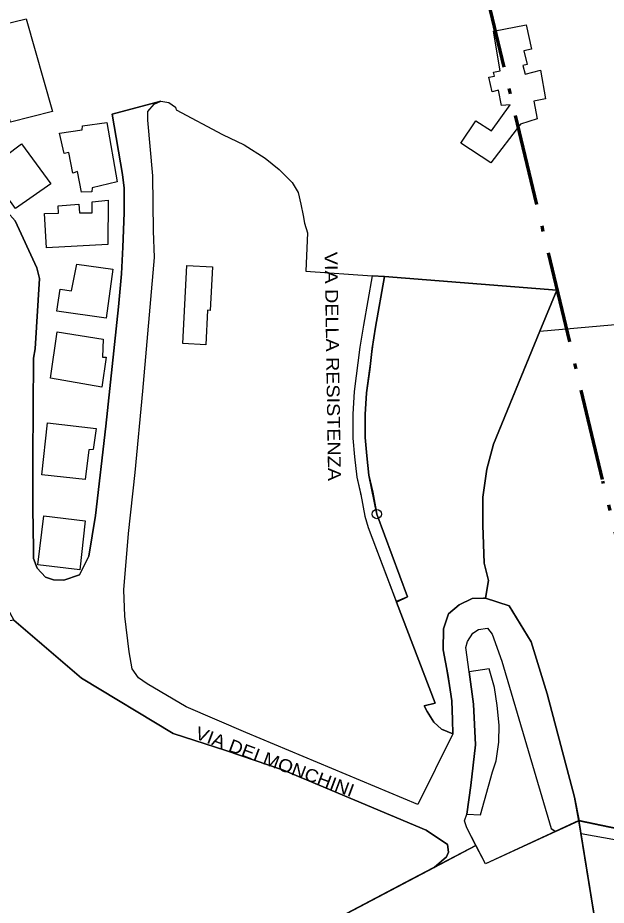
# Model space of a CAD drawing. Extents: x 654952 to 658955, y 890426 to 894481.
# Drawn here: x 657884.3 to 658012.7, y 891148.5 to 891342 of the extents above; entities that cross this region are included whole.
import ezdxf

# ---------------------------------------------------------------- set-up
doc = ezdxf.new("R2010")
doc.units = 0
doc.header["$LTSCALE"] = 4
doc.header["$PDMODE"] = 32
doc.header["$PDSIZE"] = 2
doc.linetypes.add('DOT_DASHED', pattern=[7.7, 5, -1.2, 0.3, -1.2])
for name, color, linetype, lineweight in [('1', 7, 'Continuous', 25), ('14', 7, 'Continuous', 25), ('17', 7, 'Continuous', 25), ('18', 7, 'Continuous', 25), ('19', 7, 'Continuous', 25), ('4', 7, 'Continuous', 25), ('45', 7, 'Continuous', 25), ('5', 7, 'Continuous', 25), ('55', 7, 'Continuous', 25), ('6', 7, 'Continuous', 25), ('8', 7, 'Continuous', 25), ('9', 7, 'Continuous', 25)]:
    doc.layers.add(name, color=color, linetype=linetype, lineweight=lineweight)
doc.layers.add('58', color=7, linetype='Continuous')

msp = doc.modelspace()

# ---------------------------------------------------------------- linework, layer by layer
at = {"layer": '1'}
for points in [[(657837.7, 891323.26), (657840.4, 891320.51), (657845.62, 891316.26), (657850.47, 891313.45), (657857.34, 891310.34), (657865.89, 891307.18), (657872.64, 891304.78), (657879.11, 891301.28), (657882.13, 891299.62), (657883.82, 891297.74), (657888.48, 891287.53), (657889.08, 891285.16), (657888.12, 891269.81), (657887.77, 891267.8)], [(657903.58, 891252.96), (657906.29, 891278.97), (657906.97, 891286.22), (657907.28, 891292.01), (657907.58, 891299.5), (657907.58, 891304.88), (657907.21, 891307.87), (657904.93, 891321.02), (657915.56, 891323.86)], [(657915.56, 891323.86), (657917.29, 891323.59), (657918.78, 891322.54), (657918.9, 891321.96)], [(657918.9, 891321.96), (657929.02, 891316.61), (657933.72, 891314.31), (657938.3, 891311.39), (657941.35, 891308.94), (657944.2, 891306.13), (657945.48, 891303.91), (657946.11, 891301.37), (657946.58, 891298.89), (657946.89, 891297.28), (657947.53, 891295.12), (657947.16, 891286.77)], [(657947.16, 891286.77), (657947.16, 891286.77), (657961.66, 891285.78), (657964.34, 891285.58), (658001.92, 891282.67)], [(658001.92, 891282.67), (657998.2, 891273.72), (657988.12, 891249.03)], [(657887.77, 891267.8), (657887.66, 891246.01), (657887.64, 891240.59), (657887.61, 891234.99)], [(657897.82, 891220.6), (657899.85, 891224.62), (657901.3, 891233.53), (657903.58, 891252.96)], [(657988.12, 891249.03), (657986.66, 891243.62), (657985.8, 891237.53), (657985.79, 891231.43), (657986.1, 891223.09), (657986.1, 891223.09), (657987.02, 891219.31), (657986.38, 891215.5)], [(657887.61, 891234.99), (657887.82, 891226.31), (657887.76, 891224.11), (657888.55, 891222.04), (657890.43, 891220.03), (657892.18, 891219.47), (657894.41, 891219.41), (657897.82, 891220.6)], [(657986.38, 891215.5), (657991.53, 891213.82), (657996.3, 891205.97)], [(657996.3, 891205.97), (657999.79, 891194.64), (658005.79, 891172.08), (658006.76, 891166.92)], [(658006.76, 891166.92), (658033.23, 891161.37), (658037.2, 891170.9), (658047.02, 891166.87), (658052.34, 891180.28), (658045.56, 891182.36), (658047.89, 891197.88), (658050.23, 891196.88)], [(658045.52, 891182.46), (658052.3, 891180.38), (658046.98, 891166.97), (658037.16, 891171), (658033.19, 891161.47), (658006.72, 891167.02), (658006.74, 891166.97), (658033.19, 891161.47), (658006.74, 891166.97)], [(658045.52, 891182.46), (658052.3, 891180.38), (658046.98, 891166.97), (658037.16, 891171), (658033.19, 891161.47), (658006.72, 891167.02), (658006.74, 891166.97)], [(658006.74, 891166.97), (657986.34, 891157.53), (657984.28, 891161.53), (657968.84, 891153.47), (657953.43, 891145.35)], [(658006.73, 891166.96), (657986.34, 891157.53), (657984.28, 891161.53), (657968.84, 891153.47), (657953.43, 891145.35)], [(658006.72, 891167.02), (658012.28, 891132.38), (658008.65, 891129.88), (657997.35, 891113.85), (657997.53, 891112.42), (657995.02, 891111.66), (657997.56, 891102.12), (658009.55, 891082.21)], [(658009.55, 891082.21), (657997.56, 891102.12), (657995.02, 891111.66), (657997.53, 891112.42), (657997.35, 891113.85), (658008.65, 891129.88), (658012.28, 891132.38), (658006.73, 891166.96)]]:
    msp.add_lwpolyline(points, dxfattribs=at)
at = {"layer": '14'}
msp.add_lwpolyline([(657982.82, 891199.41), (657982.05, 891204.72), (657982.4, 891206.04), (657983.6, 891207.88), (657984.84, 891208.66), (657986.83, 891208.91), (657987.79, 891207.65), (657989.91, 891201.71), (657989.91, 891201.71), (658000.67, 891165.24), (658001.7, 891164.59), (657986.34, 891157.53), (657982.28, 891165.41), (657981.78, 891166.96), (657982.32, 891168.35), (657985.28, 891168.21), (657987.87, 891177.62), (657988.67, 891179.99), (657989.24, 891184.09), (657989.34, 891187.82), (657988.9, 891192.06), (657988.3, 891196.02), (657987.16, 891200.07)], close=True, dxfattribs=at)
at = {"layer": '17'}
for points in [[(657978.08, 891161.76), (657973.4, 891164.86), (657942.34, 891177.94), (657929.71, 891182.26), (657918.26, 891185.94), (657898.29, 891198.03), (657883.47, 891210.7), (657878.12, 891209.84), (657855.72, 891210.15), (657829.85, 891209.87), (657828.3, 891222.06)], [(657953.53, 891145.36), (657975.13, 891156.76), (657977.86, 891159.09), (657978.28, 891160.13), (657978.08, 891161.76)]]:
    msp.add_lwpolyline(points, dxfattribs=at)
at = {"layer": '18'}
for points in [[(657961.66, 891285.78), (657959.76, 891275.02), (657958.99, 891270.24), (657958.99, 891270.24), (657957.75, 891260.54), (657957.46, 891255.57), (657957.45, 891250.37), (657957.79, 891246.26), (657958.31, 891241.87), (657959.2, 891237.99), (657959.17, 891238.11), (657960.02, 891233.34), (657960.76, 891230.89), (657966.88, 891214.72), (657969.35, 891215.76)], [(657961.8, 891238.58), (657960.95, 891242.32), (657960.45, 891246.53), (657960.12, 891250.48), (657960.13, 891255.49), (657960.41, 891260.27), (657961.15, 891265.34), (657961.64, 891269.89), (657962.39, 891274.58), (657964.34, 891285.58), (657961.66, 891285.78)], [(657969.35, 891215.76), (657962.65, 891233.81), (657961.8, 891238.58)], [(657988.6, 891194.04), (657988.3, 891196.02), (657987.16, 891200.07), (657982.82, 891199.41), (657983.72, 891192.35), (657984.15, 891183.49), (657983.15, 891174.64)], [(657989.34, 891187.82), (657988.9, 891192.06), (657988.6, 891194.04)], [(657983.15, 891174.64), (657982.32, 891168.35), (657985.28, 891168.21), (657987.87, 891177.62), (657988.67, 891179.99), (657989.24, 891184.09), (657989.34, 891187.82)]]:
    msp.add_lwpolyline(points, dxfattribs=at)
at = {"layer": '19'}
for points in [[(657964.34, 891285.58), (657962.39, 891274.58), (657961.64, 891269.89), (657961.15, 891265.34), (657960.41, 891260.27), (657960.13, 891255.49), (657960.12, 891250.48), (657960.45, 891246.53), (657960.95, 891242.32), (657961.8, 891238.58), (657962.65, 891233.81)], [(657994.23, 891263.99), (657998.2, 891273.72), (658001.92, 891282.67), (657964.34, 891285.58)], [(657986.38, 891215.5), (657987.02, 891219.31), (657986.1, 891223.09), (657986.1, 891223.09), (657985.79, 891231.43), (657985.8, 891237.53), (657986.66, 891243.62), (657988.12, 891249.03), (657994.23, 891263.99)], [(657962.65, 891233.81), (657969.35, 891215.76), (657966.88, 891214.72), (657975.39, 891192.57), (657972.96, 891192.01), (657973.67, 891190.77), (657975.07, 891188.45), (657976.78, 891186.91), (657979.26, 891185.89), (657979.15, 891188.93), (657979, 891193.06), (657978.13, 891198.84), (657977.14, 891204.22), (657977.21, 891208.77), (657978.31, 891212.06), (657980.61, 891214.03), (657983.45, 891215.38), (657985.9, 891215.47), (657986.38, 891215.5)]]:
    msp.add_lwpolyline(points, dxfattribs=at)
msp.add_point((657962.65, 891233.81), dxfattribs=at)
at = {"layer": '4'}
for points in [[(657886.17, 891341.82), (657891.92, 891321.58), (657882.74, 891319.3), (657877.46, 891339.66)], [(657987.49, 891310.42), (657980.99, 891314.7), (657984.23, 891319.58), (657987.68, 891317.36), (657991.73, 891323.08), (657989.86, 891322.9), (657989.22, 891326.24), (657987.85, 891325.9), (657987.08, 891329.06), (657988.32, 891329.32), (657988.08, 891330.16), (657989.54, 891330.46), (657988.13, 891339.12), (657995.24, 891340.5), (657996.38, 891335.2), (657994.71, 891334.8), (657995.43, 891331.84), (657994.51, 891331.64), (657995.01, 891329.76), (657998.34, 891330.58), (657999.48, 891324.34), (657996.91, 891323.88), (657997.63, 891320), (657994.02, 891318.86)], [(657903.75, 891319.2), (657906.05, 891306.24), (657900.56, 891304.96), (657900.54, 891304.08), (657898.26, 891304.02), (657897.41, 891308.52), (657896.35, 891308.18), (657895.51, 891312.64), (657894.44, 891312.44), (657893.49, 891316.86), (657898.43, 891317.6), (657898.47, 891318.5)], [(657883.88, 891300.46), (657877.67, 891308.94), (657885.2, 891314.52), (657891.55, 891305.84)], [(657904.02, 891292.58), (657890.59, 891291.88), (657890.17, 891299.36), (657893.22, 891299.4), (657893.14, 891301.02), (657897.68, 891301.4), (657897.83, 891299.48), (657900.6, 891299.52), (657900.56, 891301.9), (657904.04, 891302.24)], [(657905.08, 891287.22), (657903.6, 891276.54), (657892.88, 891278.04), (657893.57, 891282.84), (657896.09, 891282.48), (657897.2, 891288.32)], [(657891.48, 891263.44), (657892.96, 891273.56), (657903, 891271.98), (657902.81, 891268), (657903.6, 891268.02), (657902.67, 891261.48)], [(657889.61, 891242.36), (657890.87, 891253.74), (657901.44, 891252.44), (657900.81, 891247.88), (657899.86, 891247.82), (657899.07, 891241.36)], [(657888.73, 891222.78), (657890.04, 891233.42), (657899.08, 891232.34), (657897.91, 891221.66)]]:
    msp.add_lwpolyline(points, close=True, dxfattribs=at)
at = {"layer": '45', "linetype": 'DOT_DASHED', "lineweight": 70}
for points in [[(658011.88, 891241.38), (657961.94, 891450.62), (657946.98, 891502.99), (657940.95, 891519.94), (657920.53, 891605.37), (657908.94, 891653.27), (657885.37, 891755.88), (657877.62, 891800.36), (657869.23, 891865.26), (657864.56, 891923.48), (657863.08, 891974.59), (657864.59, 892055.62), (657871.75, 892138.2), (657882.82, 892211.71), (657888.75, 892244.36), (657949.53, 892498.78)], [(658343.4, 890537.48), (658323.23, 890567.38), (658199.11, 890752.18), (658152.38, 890823.25), (658114.5, 890887.55), (658077.53, 890971.09), (658011.97, 891240.99)]]:
    msp.add_lwpolyline(points, dxfattribs=at)
at = {"layer": '5'}
msp.add_line((658006.76, 891166.92), (658005.79, 891172.08), dxfattribs=at)
for points in [[(657914.18, 891289.74), (657913.99, 891295.59), (657913.78, 891307.57), (657912.73, 891319.7), (657912.74, 891321.57), (657914.07, 891323.16), (657915.56, 891323.86), (657904.93, 891321.02)], [(657904.93, 891321.02), (657907.21, 891307.87), (657907.58, 891304.88), (657907.58, 891299.5), (657907.28, 891292.01), (657906.97, 891286.22), (657906.29, 891278.97), (657903.58, 891252.96)], [(657887.64, 891240.59), (657887.66, 891246.01), (657887.77, 891267.8), (657888.12, 891269.81), (657889.08, 891285.16), (657888.48, 891287.53), (657883.82, 891297.74), (657882.13, 891299.62), (657875.99, 891284.64)], [(657907.46, 891217.26), (657908.47, 891229.57), (657909.99, 891242.91), (657911.63, 891260.63), (657914.18, 891289.74)], [(657875.99, 891284.64), (657877.23, 891285.16), (657878.78, 891284.6), (657879.48, 891283.39), (657879.95, 891280.84), (657880.87, 891276.71), (657880.4, 891245.81), (657879.6, 891226.27), (657879.6, 891220.39), (657882.11, 891213.26), (657883.47, 891210.7), (657898.29, 891198.03)], [(657903.58, 891252.96), (657901.3, 891233.53), (657899.85, 891224.62), (657897.82, 891220.6)], [(657897.82, 891220.6), (657894.41, 891219.41), (657892.18, 891219.47), (657890.43, 891220.03), (657888.55, 891222.04), (657887.76, 891224.11), (657887.82, 891226.31), (657887.61, 891234.99), (657887.64, 891240.59)], [(657934.11, 891186.17), (657921.09, 891191.76), (657912.6, 891196.78), (657910.66, 891198.11), (657909.28, 891200.09), (657908.66, 891203.74), (657907.73, 891211.53), (657907.46, 891217.26)], [(657986.38, 891215.5), (657985.9, 891215.47), (657983.45, 891215.38), (657980.61, 891214.03), (657978.31, 891212.06), (657977.21, 891208.77), (657977.14, 891204.22), (657978.13, 891198.84), (657979, 891193.06), (657979.15, 891188.93), (657979.26, 891185.89)], [(658005.79, 891172.08), (657999.79, 891194.64), (657996.3, 891205.97), (657991.53, 891213.82), (657986.38, 891215.5)], [(657982.82, 891199.41), (657982.05, 891204.72), (657982.4, 891206.04), (657983.6, 891207.88), (657984.84, 891208.66), (657986.83, 891208.91), (657987.79, 891207.65), (657989.91, 891201.71), (657989.91, 891201.71), (658000.67, 891165.24), (658001.66, 891164.62), (658006.73, 891166.96)], [(657984.28, 891161.53), (657982.28, 891165.41), (657981.78, 891166.96), (657982.32, 891168.35), (657983.15, 891174.64), (657984.15, 891183.49), (657983.72, 891192.35), (657982.82, 891199.41)], [(657898.29, 891198.03), (657918.26, 891185.94), (657929.71, 891182.26), (657942.34, 891177.94)], [(657979.26, 891185.89), (657971.58, 891170.51), (657934.11, 891186.17)], [(657942.34, 891177.94), (657973.4, 891164.86), (657978.08, 891161.76)], [(657978.08, 891161.76), (657978.28, 891160.13), (657977.86, 891159.09), (657975.13, 891156.76), (657984.28, 891161.53)]]:
    msp.add_lwpolyline(points, dxfattribs=at)
at = {"layer": '55'}
for points in [[(657903.58, 891252.96), (657906.29, 891278.97), (657906.97, 891286.22), (657907.28, 891292.01), (657907.58, 891299.5), (657907.58, 891304.88), (657907.21, 891307.87), (657904.93, 891321.02), (657915.56, 891323.86)], [(657915.56, 891323.86), (657917.29, 891323.59), (657918.78, 891322.54), (657918.9, 891321.96)], [(657918.9, 891321.96), (657929.02, 891316.61), (657933.72, 891314.31), (657938.3, 891311.39), (657941.35, 891308.94), (657944.2, 891306.13), (657945.48, 891303.91), (657946.11, 891301.37), (657946.58, 891298.89), (657946.89, 891297.28), (657947.53, 891295.12), (657947.16, 891286.77)], [(657865.89, 891307.18), (657872.64, 891304.78), (657879.11, 891301.28), (657882.13, 891299.62), (657883.82, 891297.74), (657888.48, 891287.53), (657889.08, 891285.16), (657888.12, 891269.81), (657887.77, 891267.8)], [(657947.16, 891286.77), (657947.16, 891286.77), (657961.66, 891285.78), (657964.34, 891285.58), (658001.92, 891282.67), (657998.2, 891273.72)], [(657998.2, 891273.72), (657988.12, 891249.03), (657986.66, 891243.62), (657985.8, 891237.53), (657985.79, 891231.43), (657986.1, 891223.09), (657987.02, 891219.31), (657986.38, 891215.5), (657991.53, 891213.82), (657996.3, 891205.97), (657999.79, 891194.64), (658005.79, 891172.08), (658006.72, 891167.02), (658033.19, 891161.47), (658037.2, 891170.9), (658047.02, 891166.87), (658052.3, 891180.38), (658045.56, 891182.36), (658047.85, 891197.98), (658050.19, 891196.98), (658051.81, 891201.21), (658050.36, 891204.78), (658043.93, 891277.75)], [(657887.77, 891267.8), (657887.66, 891246.01), (657887.64, 891240.59), (657887.61, 891234.99)], [(657897.82, 891220.6), (657899.85, 891224.62), (657901.3, 891233.53), (657903.58, 891252.96)], [(657887.61, 891234.99), (657887.82, 891226.31), (657887.76, 891224.11), (657888.55, 891222.04), (657890.43, 891220.03), (657892.18, 891219.47), (657894.41, 891219.41), (657897.82, 891220.6)]]:
    msp.add_lwpolyline(points, dxfattribs=at)
at = {"layer": '6'}
msp.add_lwpolyline([(657926.81, 891287.7), (657926.32, 891278.21), (657925.72, 891278.24), (657925.34, 891270.75), (657920.35, 891271.01), (657921.22, 891287.99)], close=True, dxfattribs=at)
at = {"layer": '8'}
msp.add_lwpolyline([(658032.36, 891159.56), (658007.19, 891164.08), (658005.79, 891172.08), (657999.79, 891194.64), (657996.3, 891205.97), (657991.53, 891213.82), (657986.38, 891215.5), (657983.45, 891215.38), (657980.61, 891214.03), (657978.31, 891212.06), (657977.21, 891208.77), (657977.14, 891204.22), (657979, 891193.06), (657979.26, 891185.89), (657976.78, 891186.91), (657975.07, 891188.45), (657973.67, 891190.77), (657972.96, 891192.01), (657975.39, 891192.57), (657966.92, 891214.62), (657969.35, 891215.76), (657962.65, 891233.81), (657960.95, 891242.32), (657960.12, 891250.48), (657960.13, 891255.49), (657960.41, 891260.27), (657962.39, 891274.58), (657964.34, 891285.58), (658001.92, 891282.67), (657998.2, 891273.72), (658071.4, 891280.17)], dxfattribs=at)
at = {"layer": '9'}
for points in [[(657914.18, 891289.74), (657913.99, 891295.59), (657913.78, 891307.57), (657912.73, 891319.7), (657912.74, 891321.57), (657914.07, 891323.16), (657915.56, 891323.86), (657917.29, 891323.59), (657918.78, 891322.54), (657918.9, 891321.96)], [(657918.9, 891321.96), (657929.02, 891316.61), (657933.72, 891314.31), (657938.31, 891311.39), (657941.35, 891308.94), (657944.2, 891306.13), (657945.48, 891303.91), (657946.11, 891301.37), (657946.58, 891298.89), (657946.89, 891297.28), (657947.53, 891295.12), (657947.16, 891286.77), (657961.66, 891285.78)], [(657907.46, 891217.26), (657908.47, 891229.57), (657909.99, 891242.91), (657911.63, 891260.63), (657914.18, 891289.74)], [(657961.66, 891285.78), (657959.76, 891275.02), (657958.99, 891270.24)], [(657958.99, 891270.24), (657957.75, 891260.54), (657957.46, 891255.57), (657957.45, 891250.37)], [(657957.45, 891250.37), (657957.79, 891246.26), (657958.31, 891241.87)], [(657958.31, 891241.87), (657959.17, 891238.11), (657960.02, 891233.34), (657960.76, 891230.89), (657966.92, 891214.62), (657975.39, 891192.57), (657972.96, 891192.01)], [(657934.11, 891186.17), (657921.09, 891191.76), (657912.6, 891196.78), (657910.66, 891198.11), (657909.28, 891200.09), (657908.66, 891203.74), (657907.73, 891211.53), (657907.46, 891217.26)], [(657972.96, 891192.01), (657973.67, 891190.77), (657975.07, 891188.45)], [(657975.07, 891188.45), (657976.78, 891186.91), (657979.26, 891185.89), (657971.58, 891170.51), (657934.11, 891186.17)]]:
    msp.add_lwpolyline(points, dxfattribs=at)

# ---------------------------------------------------------------- texts
at = {"layer": '58'}
for s, height, rotation, width, p in [('VIA DELLA RESISTENZA', 2.797, 270.88, 1.15, (657951.27, 891290.98)), ('VIA DEI MONCHINI', 2.8, 339.416, 1.1, (657922.79, 891184.96))]:
    msp.add_text(s, height=height, rotation=rotation, dxfattribs=dict(at, width=width)).set_placement(p)

doc.saveas('drawing.dxf')
